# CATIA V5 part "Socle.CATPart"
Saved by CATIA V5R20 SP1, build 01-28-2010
Part number: Socle
Publications: "Droite.2", "Droite.3", "Point D", "Point A", "Plan_Ref"
Bounding box of the stored display mesh (mm): x -20 to 20, y 0 to 240, z 0 to 0
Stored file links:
  D:\Catia\IAO\A rendre\Socle.CATPart
  D:\Catia\IAO\A rendre\Youpi.CATProduct
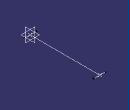
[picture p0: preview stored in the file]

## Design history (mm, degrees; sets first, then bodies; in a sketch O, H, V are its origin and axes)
Set1
  Point1 "Point A": linked copy from another document
  Point2 "Point D": linked copy from another document
  Plane1 "Plan_Ref": linked copy from another document
Body1 (main body)
  Line1: type PtPt, FirstPoint Point1, SecondPoint Point2, Support Plane1
  Line2: type PtDir, RefPoint Point1, Direction Plane1, Start -20, End 20
  Line3: type PtDir, RefPoint Point2, Direction Plane1, Start -20, End 20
